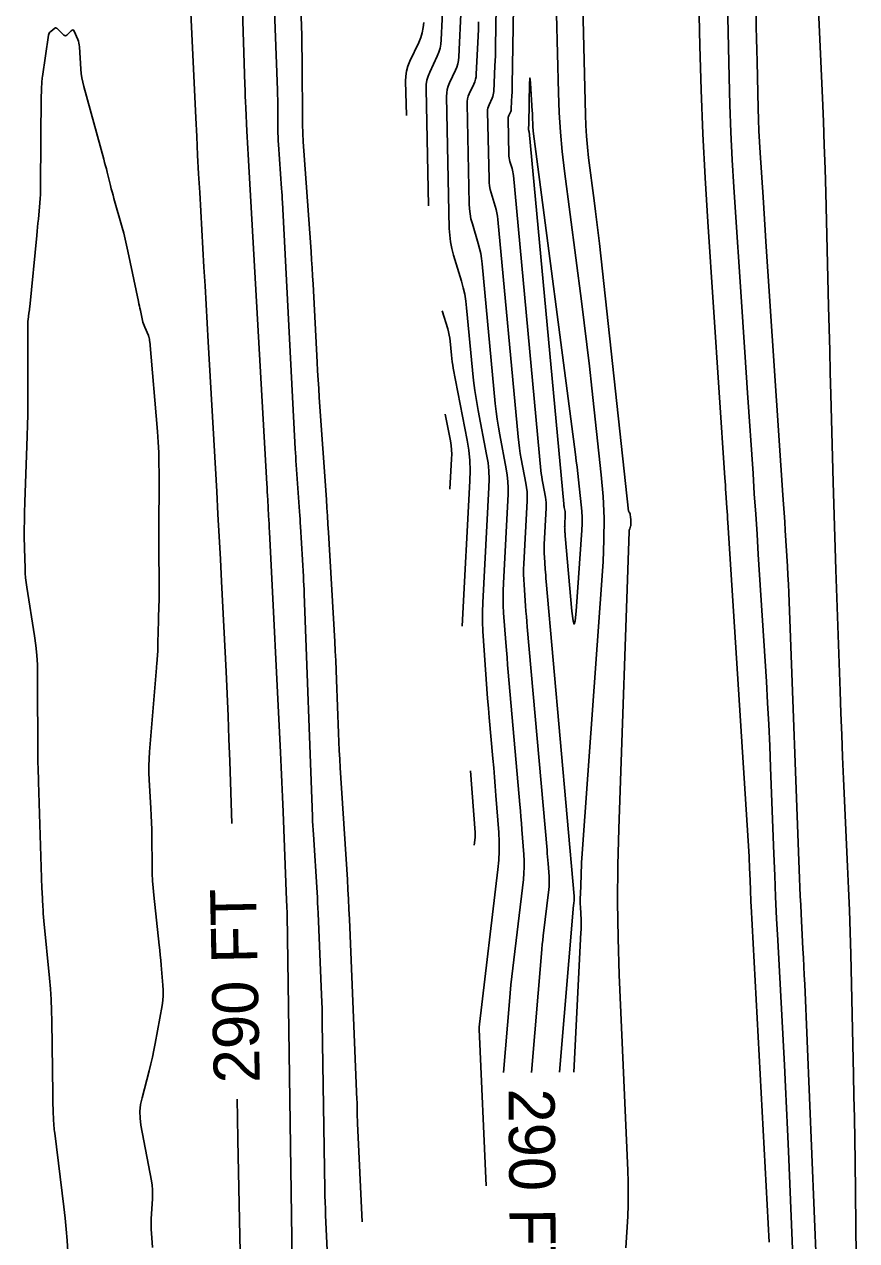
# Model space of a CAD drawing. Extents: x 1768942 to 1774819, y 723037 to 732099.
# Drawn here: x 1770847.6 to 1770956.2, y 723396.1 to 723554.8 of the extents above; entities that cross this region are included whole.
import ezdxf

# ---------------------------------------------------------------- set-up
doc = ezdxf.new("R2010")
doc.units = 0
doc.layers.add('R_Contour Annot', color=7, linetype='Continuous')
doc.layers.add('R_Contours', color=7, linetype='Continuous')

msp = doc.modelspace()

# ---------------------------------------------------------------- linework, layer by layer
at = {"layer": 'R_Contours'}
for points in [[(1770917.43, 723418.08), (1770919.26, 723439.84), (1770919.27, 723439.89), (1770919.27, 723439.94), (1770919.28, 723439.99), (1770919.28, 723440.04), (1770919.35, 723440.57), (1770919.35, 723440.61), (1770919.35, 723440.65), (1770919.35, 723440.68), (1770919.35, 723440.72), (1770919.34, 723440.87), (1770919.34, 723440.91), (1770919.33, 723440.95), (1770919.33, 723440.98), (1770919.33, 723441.02), (1770915.7, 723482.09), (1770915.66, 723482.49), (1770915.63, 723482.89), (1770915.6, 723483.29), (1770915.57, 723483.69), (1770915.45, 723485.29), (1770915.43, 723485.69), (1770915.42, 723486.09), (1770915.42, 723486.49), (1770915.43, 723486.89), (1770915.68, 723491.69), (1770915.69, 723492.04), (1770915.68, 723492.38), (1770915.65, 723492.72), (1770915.59, 723493.07), (1770915.24, 723494.9), (1770915.16, 723495.32), (1770915.1, 723495.74), (1770915.04, 723496.16), (1770915, 723496.58), (1770911.41, 723535.03), (1770911.39, 723535.27), (1770911.35, 723535.5), (1770911.29, 723535.73), (1770911.23, 723535.96), (1770910.96, 723536.87), (1770910.9, 723537.1), (1770910.85, 723537.33), (1770910.82, 723537.56), (1770910.81, 723537.8), (1770910.72, 723542.39), (1770910.72, 723542.51), (1770910.74, 723542.63), (1770910.77, 723542.75), (1770910.82, 723542.86), (1770911.02, 723543.3), (1770911.07, 723543.41), (1770911.1, 723543.53), (1770911.13, 723543.64), (1770911.14, 723543.77), (1770911.22, 723545.51), (1770911.23, 723545.84), (1770911.25, 723546.17), (1770911.25, 723546.51), (1770911.26, 723546.84), (1770912.01, 723589.98)], [(1770882.61, 723390.37), (1770881.89, 723438.62), (1770881.89, 723438.68), (1770881.89, 723438.74), (1770881.89, 723438.81), (1770881.89, 723438.87), (1770881.85, 723439.63), (1770881.85, 723439.68), (1770881.85, 723439.73), (1770881.85, 723439.78), (1770881.84, 723439.82), (1770881.81, 723440.36), (1770881.81, 723440.4), (1770881.81, 723440.45), (1770881.8, 723440.49), (1770881.8, 723440.53), (1770881.37, 723452.05), (1770881.3, 723453.99), (1770881.22, 723455.92), (1770881.13, 723457.85), (1770881.04, 723459.79), (1770879.59, 723488.56), (1770879.56, 723489.09), (1770879.53, 723489.61), (1770879.5, 723490.13), (1770879.47, 723490.66), (1770879.36, 723492.75), (1770879.33, 723493.27), (1770879.3, 723493.8), (1770879.27, 723494.32), (1770879.24, 723494.84), (1770876.8, 723537.8), (1770876.76, 723538.56), (1770876.72, 723539.32), (1770876.68, 723540.08), (1770876.64, 723540.84), (1770876.5, 723543.88), (1770876.47, 723544.64), (1770876.43, 723545.4), (1770876.41, 723546.16), (1770876.38, 723546.91), (1770875.08, 723588.38)], [(1770913.77, 723418.05), (1770915.08, 723433.56), (1770915.13, 723434.13), (1770915.18, 723434.71), (1770915.24, 723435.28), (1770915.31, 723435.85), (1770916.03, 723441.89), (1770916.07, 723442.31), (1770916.09, 723442.74), (1770916.09, 723443.16), (1770916.06, 723443.59), (1770915.94, 723445.3), (1770915.9, 723445.73), (1770915.87, 723446.15), (1770915.83, 723446.58), (1770915.8, 723447.01), (1770913.22, 723476.17), (1770913.16, 723476.85), (1770913.1, 723477.53), (1770913.05, 723478.22), (1770913, 723478.9), (1770912.8, 723481.64), (1770912.76, 723482.32), (1770912.74, 723483), (1770912.74, 723483.69), (1770912.77, 723484.37), (1770913.2, 723492.58), (1770913.21, 723493.17), (1770913.19, 723493.76), (1770913.13, 723494.34), (1770913.04, 723494.92), (1770912.43, 723498.06), (1770912.3, 723498.77), (1770912.19, 723499.49), (1770912.1, 723500.22), (1770912.02, 723500.94), (1770909.38, 723529.28), (1770909.33, 723529.73), (1770909.25, 723530.18), (1770909.15, 723530.62), (1770909.03, 723531.06), (1770908.51, 723532.8), (1770908.39, 723533.23), (1770908.3, 723533.68), (1770908.25, 723534.12), (1770908.23, 723534.58), (1770908.04, 723543.38), (1770908.05, 723543.61), (1770908.09, 723543.84), (1770908.15, 723544.06), (1770908.23, 723544.27), (1770908.63, 723545.12), (1770908.72, 723545.34), (1770908.79, 723545.56), (1770908.83, 723545.78), (1770908.85, 723546.01), (1770909.01, 723549.36), (1770909.04, 723549.99), (1770909.06, 723550.63), (1770909.08, 723551.26), (1770909.09, 723551.9), (1770909.7, 723587.17)], [(1770934.97, 723587.55), (1770935.75, 723551.94), (1770935.91, 723546.2), (1770936.13, 723540.47), (1770936.42, 723534.73), (1770936.77, 723529), (1770938.99, 723495.6), (1770939.03, 723495.12), (1770939.06, 723494.63), (1770939.09, 723494.14), (1770939.12, 723493.66), (1770939.25, 723491.71), (1770939.28, 723491.22), (1770939.32, 723490.74), (1770939.35, 723490.25), (1770939.38, 723489.76), (1770942.15, 723446.19), (1770942.18, 723445.65), (1770942.21, 723445.11), (1770942.23, 723444.58), (1770942.25, 723444.04), (1770942.33, 723441.89), (1770942.36, 723441.35), (1770942.38, 723440.81), (1770942.4, 723440.28), (1770942.43, 723439.74), (1770944.77, 723395.9)], [(1770919.98, 723576.7), (1770920.8, 723542.96), (1770920.85, 723541.55), (1770920.94, 723540.15), (1770921.07, 723538.75), (1770921.23, 723537.35), (1770921.96, 723531.76), (1770922.14, 723530.36), (1770922.31, 723528.97), (1770922.47, 723527.57), (1770922.63, 723526.17), (1770926.44, 723491.27), (1770926.45, 723491.23), (1770926.46, 723491.2), (1770926.48, 723491.16), (1770926.5, 723491.13), (1770926.59, 723491.01), (1770926.61, 723490.98), (1770926.63, 723490.94), (1770926.64, 723490.91), (1770926.65, 723490.87), (1770926.69, 723490.44), (1770926.7, 723490.36), (1770926.71, 723490.28), (1770926.71, 723490.19), (1770926.72, 723490.11), (1770926.75, 723489.63), (1770926.75, 723489.54), (1770926.74, 723489.45), (1770926.73, 723489.36), (1770926.7, 723489.28), (1770926.58, 723488.93), (1770926.55, 723488.85), (1770926.53, 723488.76), (1770926.52, 723488.67), (1770926.51, 723488.58), (1770925.15, 723449.81), (1770925.03, 723445.06), (1770925, 723440.3), (1770925.07, 723435.54), (1770925.23, 723430.79), (1770926.34, 723405.25), (1770926.39, 723403.75), (1770926.4, 723402.26), (1770926.38, 723400.76), (1770926.32, 723399.26), (1770926.1, 723395.17)], [(1770879.49, 723576.07), (1770880.63, 723546.18), (1770880.65, 723545.57), (1770880.66, 723544.96), (1770880.67, 723544.35), (1770880.68, 723543.74), (1770880.69, 723541.06), (1770880.69, 723540.57), (1770880.71, 723540.07), (1770880.73, 723539.58), (1770880.76, 723539.08), (1770881.17, 723533.36), (1770881.21, 723532.91), (1770881.24, 723532.45), (1770881.26, 723531.99), (1770881.29, 723531.53), (1770882.96, 723499.38), (1770882.99, 723498.85), (1770883.02, 723498.33), (1770883.05, 723497.8), (1770883.09, 723497.28), (1770883.51, 723491.2), (1770883.55, 723490.71), (1770883.58, 723490.22), (1770883.61, 723489.73), (1770883.64, 723489.24), (1770884.01, 723482.75), (1770884.04, 723482.18), (1770884.07, 723481.61), (1770884.1, 723481.03), (1770884.12, 723480.46), (1770885.2, 723451.42), (1770885.22, 723450.83), (1770885.25, 723450.24), (1770885.28, 723449.66), (1770885.32, 723449.07), (1770885.8, 723441.52), (1770885.84, 723440.85), (1770885.87, 723440.18), (1770885.91, 723439.51), (1770885.94, 723438.83), (1770886.38, 723428.15), (1770886.42, 723427.25), (1770886.45, 723426.35), (1770886.47, 723425.45), (1770886.48, 723424.56), (1770886.81, 723402.76), (1770886.83, 723401.93), (1770886.85, 723401.1), (1770886.88, 723400.26), (1770886.91, 723399.43), (1770887.45, 723387.59)], [(1770947.95, 723391.82), (1770947.3, 723407.78), (1770947.18, 723410.58), (1770947.05, 723413.37), (1770946.91, 723416.17), (1770946.77, 723418.97), (1770945.9, 723435.3), (1770945.75, 723438.11), (1770945.62, 723440.93), (1770945.5, 723443.74), (1770945.39, 723446.55), (1770944.97, 723457.81), (1770944.86, 723460.62), (1770944.73, 723463.43), (1770944.58, 723466.24), (1770944.41, 723469.05), (1770943.36, 723485.6), (1770943.19, 723488.24), (1770943.02, 723490.88), (1770942.84, 723493.52), (1770942.67, 723496.16), (1770941.97, 723506.7), (1770941.79, 723509.34), (1770941.61, 723511.98), (1770941.44, 723514.62), (1770941.26, 723517.25), (1770940.18, 723533.5), (1770939.96, 723537.09), (1770939.78, 723540.68), (1770939.64, 723544.27), (1770939.54, 723547.86), (1770939.16, 723565.48)], [(1770868.9, 723565.42), (1770869.98, 723542.58), (1770870.1, 723540.14), (1770870.22, 723537.7), (1770870.35, 723535.27), (1770870.49, 723532.83), (1770871.04, 723523.08), (1770871.18, 723520.65), (1770871.32, 723518.21), (1770871.45, 723515.77), (1770871.59, 723513.34), (1770872.71, 723493.8), (1770872.87, 723490.87), (1770873.03, 723487.94), (1770873.19, 723485.01), (1770873.34, 723482.08), (1770873.93, 723470.36), (1770874.07, 723467.43), (1770874.2, 723464.5), (1770874.31, 723461.57), (1770874.41, 723458.64), (1770874.66, 723450.52)], [(1770891.67, 723398.53), (1770891.08, 723411.39), (1770891.07, 723411.65), (1770891.06, 723411.9), (1770891.05, 723412.16), (1770891.05, 723412.42), (1770891.03, 723413.44), (1770891.03, 723413.7), (1770891.02, 723413.96), (1770891.01, 723414.21), (1770891, 723414.47), (1770890.02, 723438.03), (1770889.96, 723439.33), (1770889.9, 723440.63), (1770889.83, 723441.92), (1770889.75, 723443.22), (1770888.82, 723457.77), (1770888.76, 723458.91), (1770888.69, 723460.04), (1770888.64, 723461.17), (1770888.6, 723462.31), (1770888.34, 723469.24), (1770888.29, 723470.5), (1770888.23, 723471.76), (1770888.17, 723473.01), (1770888.1, 723474.27), (1770887.28, 723488.49), (1770887.22, 723489.56), (1770887.15, 723490.64), (1770887.08, 723491.71), (1770887.01, 723492.78), (1770886.08, 723506.1), (1770886.01, 723507.24), (1770885.93, 723508.39), (1770885.87, 723509.54), (1770885.8, 723510.69), (1770885.27, 723520.88), (1770885.22, 723521.94), (1770885.15, 723523), (1770885.09, 723524.05), (1770885.01, 723525.11), (1770884.06, 723538.28), (1770883.99, 723539.42), (1770883.93, 723540.56), (1770883.9, 723541.7), (1770883.89, 723542.84), (1770883.87, 723549.01), (1770883.86, 723550.41), (1770883.83, 723551.82), (1770883.8, 723553.23), (1770883.75, 723554.64), (1770883.52, 723560.67)], [(1770900.34, 723531.08), (1770900.03, 723546.35), (1770900.05, 723546.92), (1770900.13, 723547.47), (1770900.28, 723548), (1770900.49, 723548.52), (1770901.46, 723550.59), (1770901.68, 723551.11), (1770901.84, 723551.64), (1770901.95, 723552.19), (1770902, 723552.75), (1770902.38, 723560.89)], [(1770956.19, 723389.82), (1770955.98, 723406.45), (1770955.94, 723409.28), (1770955.89, 723412.1), (1770955.84, 723414.92), (1770955.78, 723417.75), (1770955.41, 723433.47), (1770955.33, 723436.33), (1770955.24, 723439.19), (1770955.13, 723442.05), (1770955.01, 723444.91), (1770954.49, 723456.35), (1770954.36, 723459.2), (1770954.24, 723462.06), (1770954.13, 723464.92), (1770954.03, 723467.78), (1770953.48, 723483.58), (1770953.38, 723486.45), (1770953.29, 723489.31), (1770953.21, 723492.17), (1770953.13, 723495.04), (1770952.82, 723506.49), (1770952.74, 723509.36), (1770952.67, 723512.22), (1770952.59, 723515.08), (1770952.52, 723517.95), (1770952.15, 723532.81), (1770952.07, 723535.9), (1770951.97, 723539), (1770951.85, 723542.09), (1770951.72, 723545.19), (1770951.17, 723557.57)], [(1770904.59, 723557.05), (1770904.29, 723550.51), (1770904.24, 723550.06), (1770904.16, 723549.61), (1770904.03, 723549.18), (1770903.85, 723548.76), (1770903.07, 723547.11), (1770902.9, 723546.69), (1770902.78, 723546.26), (1770902.72, 723545.82), (1770902.7, 723545.36), (1770903.05, 723528.13), (1770903.1, 723527.25), (1770903.21, 723526.38), (1770903.38, 723525.51), (1770903.61, 723524.66), (1770904.63, 723521.25), (1770904.87, 723520.4), (1770905.06, 723519.54), (1770905.21, 723518.66), (1770905.31, 723517.78), (1770906.07, 723509.65), (1770906.21, 723508.32), (1770906.38, 723507), (1770906.59, 723505.69), (1770906.82, 723504.37), (1770907.92, 723498.64), (1770908.1, 723497.58), (1770908.2, 723496.5), (1770908.24, 723495.43), (1770908.22, 723494.35), (1770907.43, 723479.33), (1770907.39, 723478.08), (1770907.38, 723476.83), (1770907.41, 723475.58), (1770907.49, 723474.32), (1770907.86, 723469.32), (1770907.95, 723468.07), (1770908.05, 723466.82), (1770908.16, 723465.57), (1770908.26, 723464.32), (1770908.73, 723458.98), (1770908.84, 723457.78), (1770908.94, 723456.57), (1770909.04, 723455.37), (1770909.13, 723454.16), (1770909.49, 723449.33), (1770909.56, 723448.13), (1770909.56, 723446.92), (1770909.5, 723445.72), (1770909.39, 723444.51), (1770906.99, 723424.35), (1770906.98, 723424.29), (1770906.97, 723424.24), (1770906.97, 723424.18), (1770906.96, 723424.12), (1770906.94, 723423.89), (1770906.94, 723423.84), (1770906.94, 723423.78), (1770906.94, 723423.72), (1770906.94, 723423.67), (1770907.87, 723403.24)], [(1770917.04, 723556.1), (1770917.28, 723545.84), (1770917.38, 723543.27), (1770917.54, 723540.71), (1770917.77, 723538.16), (1770918.07, 723535.61), (1770920.29, 723518.63), (1770920.65, 723515.8), (1770921, 723512.98), (1770921.33, 723510.15), (1770921.64, 723507.32), (1770922.88, 723496), (1770923.13, 723493.17), (1770923.24, 723490.34), (1770923.23, 723487.5), (1770923.1, 723484.66), (1770920.35, 723445.97), (1770920.31, 723445.41), (1770920.28, 723444.86), (1770920.26, 723444.31), (1770920.23, 723443.75), (1770920.15, 723441.27), (1770920.14, 723440.85), (1770920.13, 723440.43), (1770920.14, 723440.02), (1770920.15, 723439.6), (1770920.23, 723437.93), (1770920.24, 723437.52), (1770920.24, 723437.1), (1770920.24, 723436.68), (1770920.22, 723436.27), (1770919.28, 723418.09)], [(1770943.07, 723555.92), (1770943.1, 723554.41), (1770943.14, 723552.91), (1770943.17, 723551.41), (1770943.2, 723549.9), (1770943.34, 723543.78), (1770943.38, 723542.33), (1770943.43, 723540.88), (1770943.51, 723539.44), (1770943.59, 723537.99), (1770943.98, 723532.22), (1770944.08, 723530.77), (1770944.17, 723529.33), (1770944.27, 723527.89), (1770944.36, 723526.44), (1770946.57, 723493.34), (1770946.65, 723492.18), (1770946.72, 723491.02), (1770946.8, 723489.86), (1770946.87, 723488.71), (1770947.17, 723484.07), (1770947.23, 723482.91), (1770947.3, 723481.75), (1770947.35, 723480.59), (1770947.4, 723479.43), (1770948.74, 723443.33), (1770948.78, 723442.19), (1770948.83, 723441.04), (1770948.89, 723439.89), (1770948.95, 723438.74), (1770949.19, 723434.15), (1770949.25, 723433), (1770949.31, 723431.85), (1770949.36, 723430.71), (1770949.41, 723429.56), (1770950.93, 723392.61)], [(1770899.72, 723555), (1770899.65, 723554.33), (1770899.52, 723553.67), (1770899.33, 723553.03), (1770899.07, 723552.41), (1770897.91, 723549.94), (1770897.66, 723549.32), (1770897.48, 723548.67), (1770897.38, 723548.02), (1770897.35, 723547.34), (1770897.45, 723542.85)], [(1770910.11, 723418.02), (1770910.89, 723427.27), (1770910.98, 723428.37), (1770911.09, 723429.47), (1770911.21, 723430.57), (1770911.33, 723431.66), (1770912.71, 723443.2), (1770912.79, 723444.01), (1770912.82, 723444.83), (1770912.82, 723445.65), (1770912.78, 723446.46), (1770912.53, 723449.73), (1770912.47, 723450.55), (1770912.4, 723451.36), (1770912.34, 723452.18), (1770912.27, 723453), (1770910.74, 723470.24), (1770910.66, 723471.21), (1770910.58, 723472.17), (1770910.5, 723473.14), (1770910.43, 723474.11), (1770910.14, 723477.98), (1770910.08, 723478.95), (1770910.06, 723479.92), (1770910.06, 723480.88), (1770910.1, 723481.85), (1770910.71, 723493.46), (1770910.73, 723494.3), (1770910.7, 723495.13), (1770910.61, 723495.96), (1770910.48, 723496.78), (1770909.63, 723501.21), (1770909.45, 723502.23), (1770909.29, 723503.25), (1770909.16, 723504.27), (1770909.05, 723505.3), (1770907.35, 723523.53), (1770907.27, 723524.2), (1770907.16, 723524.86), (1770907.01, 723525.51), (1770906.83, 723526.16), (1770906.06, 723528.73), (1770905.88, 723529.37), (1770905.76, 723530.03), (1770905.68, 723530.69), (1770905.64, 723531.35), (1770905.37, 723544.37), (1770905.38, 723544.71), (1770905.43, 723545.05), (1770905.52, 723545.37), (1770905.65, 723545.69), (1770906.24, 723546.94), (1770906.37, 723547.26), (1770906.47, 723547.59), (1770906.54, 723547.92), (1770906.57, 723548.26), (1770906.8, 723553.2), (1770906.84, 723554.14), (1770906.87, 723555.08)], [(1770853.27, 723394.67), (1770853.18, 723396.12), (1770853.06, 723397.58), (1770852.92, 723399.03), (1770852.76, 723400.49), (1770851.57, 723410.1), (1770851.55, 723410.34), (1770851.52, 723410.58), (1770851.5, 723410.83), (1770851.48, 723411.07), (1770851.42, 723412.04), (1770851.41, 723412.29), (1770851.39, 723412.53), (1770851.38, 723412.77), (1770851.37, 723413.02), (1770851.34, 723414.13), (1770851.33, 723414.4), (1770851.32, 723414.66), (1770851.31, 723414.93), (1770851.31, 723415.2), (1770851.2, 723424.71), (1770851.17, 723426.12), (1770851.11, 723427.53), (1770851.02, 723428.93), (1770850.89, 723430.34), (1770850.16, 723437.83), (1770850.11, 723438.3), (1770850.08, 723438.76), (1770850.05, 723439.23), (1770850.02, 723439.69), (1770849.93, 723441.56), (1770849.91, 723442.03), (1770849.89, 723442.49), (1770849.87, 723442.96), (1770849.86, 723443.43), (1770849.47, 723455.96), (1770849.47, 723456.12), (1770849.46, 723456.27), (1770849.45, 723456.42), (1770849.45, 723456.57), (1770849.42, 723457.19), (1770849.42, 723457.34), (1770849.41, 723457.49), (1770849.41, 723457.63), (1770849.4, 723457.78), (1770849.38, 723458.37), (1770849.38, 723458.52), (1770849.37, 723458.66), (1770849.37, 723458.81), (1770849.37, 723458.96), (1770849.35, 723469.95), (1770849.32, 723471.22), (1770849.25, 723472.49), (1770849.12, 723473.75), (1770848.94, 723475.01), (1770847.93, 723481.35), (1770847.85, 723481.95), (1770847.78, 723482.56), (1770847.73, 723483.17), (1770847.71, 723483.78), (1770847.63, 723486.43), (1770847.62, 723486.93), (1770847.61, 723487.44), (1770847.61, 723487.94), (1770847.61, 723488.45), (1770847.63, 723490.47), (1770847.64, 723490.98), (1770847.65, 723491.48), (1770847.66, 723491.99), (1770847.68, 723492.49), (1770847.95, 723499.72), (1770848, 723501.09), (1770848.03, 723502.47), (1770848.05, 723503.84), (1770848.06, 723505.22), (1770848.05, 723515.41), (1770848.05, 723515.62), (1770848.06, 723515.83), (1770848.08, 723516.04), (1770848.1, 723516.24), (1770848.21, 723517.08), (1770848.24, 723517.29), (1770848.27, 723517.5), (1770848.29, 723517.71), (1770848.31, 723517.92), (1770849.24, 723527.23), (1770849.29, 723527.76), (1770849.34, 723528.3), (1770849.39, 723528.83), (1770849.44, 723529.36), (1770849.63, 723531.49), (1770849.67, 723532.03), (1770849.71, 723532.56), (1770849.73, 723533.09), (1770849.74, 723533.63), (1770849.82, 723545.58), (1770849.83, 723545.78), (1770849.83, 723545.98), (1770849.84, 723546.18), (1770849.85, 723546.38), (1770849.89, 723547.18), (1770849.9, 723547.38), (1770849.92, 723547.57), (1770849.94, 723547.77), (1770849.97, 723547.97), (1770850.78, 723553.36), (1770850.81, 723553.49), (1770850.87, 723553.61), (1770850.94, 723553.72), (1770851.05, 723553.82), (1770851.6, 723554.25), (1770851.66, 723554.29), (1770851.72, 723554.3), (1770851.78, 723554.28), (1770851.84, 723554.24), (1770852.77, 723553.36), (1770852.87, 723553.29), (1770852.97, 723553.26), (1770853.06, 723553.29), (1770853.16, 723553.36), (1770853.72, 723553.92), (1770853.84, 723554.01), (1770853.94, 723554.03), (1770854.03, 723553.98), (1770854.11, 723553.85), (1770854.57, 723552.79), (1770854.66, 723552.55), (1770854.73, 723552.31), (1770854.78, 723552.07), (1770854.81, 723551.82), (1770854.99, 723548.9), (1770855.04, 723548.33), (1770855.12, 723547.77), (1770855.23, 723547.21), (1770855.37, 723546.66), (1770857.97, 723537.18), (1770858.09, 723536.75), (1770858.2, 723536.32), (1770858.31, 723535.89), (1770858.42, 723535.47), (1770858.85, 723533.75), (1770858.96, 723533.32), (1770859.07, 723532.9), (1770859.19, 723532.47), (1770859.3, 723532.04), (1770860.37, 723528.27), (1770860.58, 723527.5), (1770860.77, 723526.72), (1770860.96, 723525.94), (1770861.13, 723525.16), (1770862.49, 723518.6), (1770862.56, 723518.31), (1770862.62, 723518.01), (1770862.68, 723517.72), (1770862.75, 723517.43), (1770863.04, 723516.11), (1770863.09, 723515.89), (1770863.16, 723515.68), (1770863.23, 723515.47), (1770863.32, 723515.26), (1770863.8, 723514.15), (1770863.82, 723514.09), (1770863.85, 723514.03), (1770863.86, 723513.96), (1770863.88, 723513.9), (1770863.93, 723513.64), (1770863.95, 723513.58), (1770863.96, 723513.52), (1770863.96, 723513.45), (1770863.97, 723513.39), (1770864.97, 723501.63), (1770865.07, 723500.27), (1770865.14, 723498.9), (1770865.17, 723497.54), (1770865.18, 723496.17), (1770865.14, 723487.96)], [(1770902.13, 723517.37), (1770902.84, 723515.02), (1770902.95, 723514.63), (1770903.03, 723514.23), (1770903.1, 723513.83), (1770903.15, 723513.42), (1770903.32, 723511.62), (1770903.36, 723511.18), (1770903.42, 723510.75), (1770903.49, 723510.32), (1770903.57, 723509.89), (1770905.37, 723500.5), (1770905.58, 723499.19), (1770905.71, 723497.88), (1770905.76, 723496.56), (1770905.73, 723495.23), (1770904.74, 723476.27)], [(1770902.52, 723503.9), (1770903.19, 723500.42), (1770903.28, 723499.84), (1770903.34, 723499.26), (1770903.36, 723498.67), (1770903.35, 723498.09), (1770903.14, 723494.12)], [(1770865.14, 723487.96), (1770865.18, 723480.06), (1770865.18, 723479.72), (1770865.18, 723479.39), (1770865.17, 723479.06), (1770865.16, 723478.73), (1770865.12, 723477.4), (1770865.11, 723477.07), (1770865.1, 723476.74), (1770865.1, 723476.41), (1770865.09, 723476.07), (1770865.04, 723473.55), (1770865.04, 723473.32), (1770865.03, 723473.09), (1770865.01, 723472.86), (1770865, 723472.64), (1770864.92, 723471.73), (1770864.91, 723471.5), (1770864.89, 723471.28), (1770864.87, 723471.05), (1770864.85, 723470.82), (1770863.94, 723459.88), (1770863.88, 723458.96), (1770863.86, 723458.03), (1770863.86, 723457.11), (1770863.9, 723456.19), (1770864.12, 723452.49), (1770864.17, 723451.57), (1770864.2, 723450.64), (1770864.23, 723449.72), (1770864.24, 723448.79), (1770864.28, 723444.94), (1770864.3, 723443.99), (1770864.34, 723443.04), (1770864.41, 723442.1), (1770864.5, 723441.15), (1770865.21, 723434.66), (1770865.28, 723434), (1770865.35, 723433.34), (1770865.41, 723432.69), (1770865.47, 723432.03), (1770865.7, 723429.4), (1770865.74, 723428.75), (1770865.73, 723428.09), (1770865.68, 723427.44), (1770865.58, 723426.79), (1770864.69, 723421.83), (1770864.52, 723420.94), (1770864.33, 723420.04), (1770864.12, 723419.15), (1770863.9, 723418.26), (1770862.97, 723414.72), (1770862.78, 723413.84), (1770862.7, 723412.94), (1770862.72, 723412.05), (1770862.83, 723411.15), (1770864.18, 723403.89), (1770864.27, 723403.31), (1770864.32, 723402.73), (1770864.34, 723402.14), (1770864.32, 723401.55), (1770864.16, 723398.95), (1770864.14, 723398.47), (1770864.14, 723398), (1770864.15, 723397.53), (1770864.18, 723397.06), (1770864.32, 723395.18)], [(1770906.29, 723447.69), (1770906.41, 723448.68), (1770906.42, 723448.84), (1770906.43, 723449.01), (1770906.43, 723449.17), (1770906.42, 723449.34), (1770905.82, 723457.36)], [(1770875.38, 723414.53), (1770875.43, 723412.12), (1770875.48, 723409.24), (1770875.89, 723388.35)]]:
    msp.add_lwpolyline(points, dxfattribs=at)
msp.add_lwpolyline([(1770918.17, 723488.13), (1770918.16, 723488.25), (1770918.15, 723488.37), (1770918.14, 723488.48), (1770918.1, 723488.95), (1770918.1, 723489.06), (1770918.09, 723489.18), (1770918.1, 723489.3), (1770918.1, 723489.41), (1770918.17, 723490.81), (1770918.18, 723490.91), (1770918.17, 723491.01), (1770918.16, 723491.11), (1770918.15, 723491.21), (1770918.04, 723491.74), (1770918.02, 723491.86), (1770918, 723491.98), (1770917.99, 723492.11), (1770917.97, 723492.23), (1770913.45, 723540.78), (1770913.44, 723540.8), (1770913.44, 723540.82), (1770913.44, 723540.84), (1770913.43, 723540.86), (1770913.41, 723540.94), (1770913.4, 723540.96), (1770913.4, 723540.98), (1770913.4, 723541), (1770913.4, 723541.02), (1770913.39, 723541.4), (1770913.39, 723541.41), (1770913.39, 723541.42), (1770913.39, 723541.43), (1770913.4, 723541.44), (1770913.41, 723541.48), (1770913.42, 723541.49), (1770913.42, 723541.5), (1770913.42, 723541.51), (1770913.42, 723541.52), (1770913.43, 723541.66), (1770913.43, 723541.69), (1770913.43, 723541.72), (1770913.43, 723541.75), (1770913.43, 723541.78), (1770913.53, 723547.09), (1770913.54, 723547.6), (1770913.57, 723547.77), (1770913.6, 723547.6), (1770913.64, 723547.09), (1770913.88, 723543.42), (1770913.89, 723543.2), (1770913.9, 723542.99), (1770913.91, 723542.77), (1770913.92, 723542.56), (1770913.94, 723541.69), (1770913.95, 723541.48), (1770913.96, 723541.26), (1770913.98, 723541.05), (1770914.01, 723540.83), (1770919.51, 723498.64), (1770919.62, 723497.82), (1770919.72, 723496.99), (1770919.81, 723496.17), (1770919.91, 723495.35), (1770920.26, 723492.06), (1770920.34, 723491.24), (1770920.37, 723490.41), (1770920.37, 723489.59), (1770920.33, 723488.76), (1770919.58, 723478.2), (1770919.46, 723476.94), (1770919.33, 723476.52), (1770919.19, 723476.94), (1770919.04, 723478.2), (1770918.18, 723488.02)], close=True, dxfattribs=at)

# ---------------------------------------------------------------- texts
at = {"layer": 'R_Contour Annot'}
for rotation, p in [(91.1496, (1770878.34, 723416.69)), (270.4204, (1770910.78, 723415.92))]:
    msp.add_text('290 FT', height=6, rotation=rotation, dxfattribs=at).set_placement(p)

doc.saveas('drawing.dxf')
